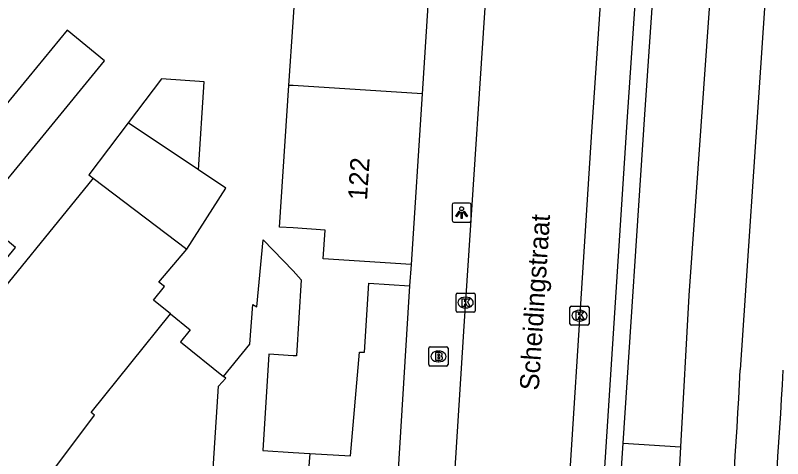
# Model space of a CAD drawing. Extents: x 160158 to 160921, y 381517 to 382041.
# Drawn here: x 160485.46 to 160525.63, y 381829.34 to 381852.53 of the extents above; entities that cross this region are included whole.
import ezdxf

# ---------------------------------------------------------------- set-up
doc = ezdxf.new("R2010")
doc.units = 0
for name, color, linetype in [('IMGEO_Berm_groen', 7, 'Continuous'), ('IMGEO_Berm_open', 7, 'Continuous'), ('IMGEO_Brandkraan', 7, 'Continuous'), ('IMGEO_Kolk', 7, 'Continuous'), ('IMGEO_Lichtpunt', 7, 'Continuous'), ('IMGEO_Openbare_ruimte_label', 7, 'Continuous'), ('IMGEO_Pand', 7, 'Continuous'), ('IMGEO_Pand_nummerreeks', 7, 'Continuous'), ('IMGEO_Parkeervlak_open', 7, 'Continuous'), ('IMGEO_Rijbaan_lokaal_open', 7, 'Continuous'), ('IMGEO_Voetpad_open', 7, 'Continuous')]:
    doc.layers.add(name, color=color, linetype=linetype)

msp = doc.modelspace()

# ---------------------------------------------------------------- linework, layer by layer
at = {"layer": 'IMGEO_Berm_groen'}
for points in [[(160532.014, 381924.443), (160531.525, 381926.029), (160530.481, 381926.358), (160529.573, 381925.76), (160523.404, 381833.99)], [(160523.346, 381875.055), (160520.714, 381837.873), (160520.28, 381829.952)], [(160520.28, 381829.952), (160520.063, 381825.981), (160517.843, 381805.586), (160514.368, 381782.689), (160510.053, 381758.978), (160509.927, 381757.953)], [(160517.274, 381830.144), (160520.28, 381829.952)]]:
    msp.add_lwpolyline(points, dxfattribs=at)
for centre, radius, start, end in [((160092.55, 381856.358), 431.434, 350.65138, 357.02816), ((160083.837, 381858.802), 442.519, 350.5442, 356.78225), ((160153.748, 381850.796), 375.027, 349.97715, 357.39851)]:
    msp.add_arc(centre, radius, start, end, dxfattribs=at)
at = {"layer": 'IMGEO_Berm_open'}
for points in [[(160517.274, 381830.144), (160518.408, 381847.341), (160520.311, 381874.994), (160520.319, 381875.157), (160520.327, 381875.319)], [(160513.86, 381817.808), (160516.446, 381817.577), (160517.274, 381830.144)]]:
    msp.add_lwpolyline(points, dxfattribs=at)
at = {"layer": 'IMGEO_Brandkraan'}
for p, q in [((160507.106, 381834.263), (160507.106, 381835.115)), ((160507.181, 381835.189), (160508.033, 381835.189)), ((160508.107, 381835.115), (160508.107, 381834.263)), ((160507.594, 381834.969), (160507.619, 381834.969)), ((160507.617, 381834.409), (160507.592, 381834.409)), ((160508.033, 381834.189), (160507.181, 381834.189))]:
    msp.add_line(p, q, dxfattribs=at)
for points in [[(160507.106, 381834.263), (160507.106, 381835.115)], [(160507.181, 381835.189), (160508.033, 381835.189)], [(160508.107, 381835.115), (160508.107, 381834.263)], [(160507.454, 381834.889), (160507.454, 381834.489), (160507.667, 381834.489)], [(160507.685, 381834.889), (160507.454, 381834.889)], [(160507.633, 381834.808), (160507.579, 381834.808), (160507.579, 381834.732)], [(160507.579, 381834.732), (160507.632, 381834.732)], [(160507.641, 381834.656), (160507.579, 381834.656), (160507.579, 381834.575)], [(160507.579, 381834.575), (160507.641, 381834.575)], [(160508.033, 381834.189), (160507.181, 381834.189)]]:
    msp.add_lwpolyline(points, dxfattribs=at)
for centre, radius, start, end in [((160507.183, 381835.113), 0.0765, 91.552, 178.448), ((160507.183, 381835.113), 0.0765, 91.552, 178.448), ((160508.031, 381835.113), 0.0765, 1.552, 88.448), ((160508.031, 381835.113), 0.0765, 1.552, 88.448), ((160507.634, 381834.77), 0.0379, 267.8285, 90.9355), ((160507.689, 381834.744), 0.145, 59.4692, 91.5367), ((160507.714, 381834.791), 0.0922, 285.5137, 58.1501), ((160507.719, 381834.599), 0.105, 301.3115, 78.989), ((160507.642, 381834.615), 0.0404, 269.8759, 90.5077), ((160507.673, 381834.74), 0.251, 268.6676, 293.5347), ((160507.183, 381834.265), 0.0765, 181.552, 268.448), ((160507.183, 381834.265), 0.0765, 181.552, 268.448), ((160508.031, 381834.265), 0.0765, 271.552, 358.448), ((160508.031, 381834.265), 0.0765, 271.552, 358.448)]:
    msp.add_arc(centre, radius, start, end, dxfattribs=at)
for centre, major_axis, ratio, start_param, end_param in [((160507.593, 381834.689), (-0.387, 0.002), 0.722429, 4.712389, 7.853982), ((160507.618, 381834.689), (-0.39, 0.002), 0.717154, 1.570796, 4.712389)]:
    msp.add_ellipse(centre, major_axis=major_axis, ratio=ratio, start_param=start_param, end_param=end_param, dxfattribs=at)
at = {"layer": 'IMGEO_Kolk'}
for p, q in [((160508.527, 381837.08), (160508.527, 381837.932)), ((160508.602, 381838.006), (160509.454, 381838.006)), ((160509.528, 381837.932), (160509.528, 381837.08)), ((160509.015, 381837.786), (160509.04, 381837.786)), ((160509.038, 381837.226), (160509.013, 381837.226)), ((160514.489, 381836.397), (160514.489, 381837.249)), ((160514.564, 381837.323), (160515.416, 381837.323)), ((160514.977, 381837.103), (160515.002, 381837.103)), ((160515.49, 381837.249), (160515.49, 381836.397)), ((160509.454, 381837.006), (160508.602, 381837.006)), ((160515.416, 381836.323), (160514.564, 381836.323)), ((160515, 381836.543), (160514.975, 381836.543))]:
    msp.add_line(p, q, dxfattribs=at)
for points in [[(160508.527, 381837.08), (160508.527, 381837.932)], [(160508.602, 381838.006), (160509.454, 381838.006)], [(160509.528, 381837.932), (160509.528, 381837.08)], [(160508.848, 381837.706), (160508.971, 381837.706), (160508.971, 381837.555), (160509.101, 381837.706), (160509.265, 381837.706), (160509.119, 381837.555), (160509.272, 381837.306), (160509.12, 381837.306), (160509.035, 381837.47), (160508.971, 381837.403), (160508.971, 381837.306), (160508.848, 381837.306), (160508.848, 381837.706)], [(160514.489, 381836.397), (160514.489, 381837.249)], [(160514.564, 381837.323), (160515.416, 381837.323)], [(160515.49, 381837.249), (160515.49, 381836.397)], [(160509.454, 381837.006), (160508.602, 381837.006)], [(160514.81, 381837.023), (160514.933, 381837.023), (160514.933, 381836.872), (160515.063, 381837.023), (160515.227, 381837.023), (160515.081, 381836.872), (160515.234, 381836.623), (160515.082, 381836.623), (160514.997, 381836.787), (160514.933, 381836.72), (160514.933, 381836.623), (160514.81, 381836.623), (160514.81, 381837.023)], [(160515.416, 381836.323), (160514.564, 381836.323)]]:
    msp.add_lwpolyline(points, dxfattribs=at)
for centre, start, end in [((160508.604, 381837.93), 91.552, 178.448), ((160508.604, 381837.93), 91.552, 178.448), ((160509.452, 381837.93), 1.552, 88.448), ((160509.452, 381837.93), 1.552, 88.448), ((160508.604, 381837.082), 181.552, 268.448), ((160508.604, 381837.082), 181.552, 268.448), ((160509.452, 381837.082), 271.552, 358.448), ((160509.452, 381837.082), 271.552, 358.448), ((160514.566, 381837.247), 91.552, 178.448), ((160514.566, 381837.247), 91.552, 178.448), ((160515.414, 381837.247), 1.552, 88.448), ((160515.414, 381837.247), 1.552, 88.448), ((160514.566, 381836.399), 181.552, 268.448), ((160514.566, 381836.399), 181.552, 268.448), ((160515.414, 381836.399), 271.552, 358.448), ((160515.414, 381836.399), 271.552, 358.448)]:
    msp.add_arc(centre, 0.0765, start, end, dxfattribs=at)
for centre, major_axis, ratio, start_param, end_param in [((160509.014, 381837.506), (-0.387, 0.002), 0.722429, 4.712389, 7.853982), ((160509.039, 381837.506), (-0.39, 0.002), 0.717154, 1.570796, 4.712389), ((160514.976, 381836.823), (-0.387, 0.002), 0.722429, 4.712389, 7.853982), ((160515.001, 381836.823), (-0.39, 0.002), 0.717154, 1.570796, 4.712389)]:
    msp.add_ellipse(centre, major_axis=major_axis, ratio=ratio, start_param=start_param, end_param=end_param, dxfattribs=at)
at = {"layer": 'IMGEO_Lichtpunt'}
for p, q in [((160509.224, 381842.716), (160508.416, 381842.716)), ((160509.224, 381842.716), (160508.416, 381842.716)), ((160508.322, 381842.621), (160508.322, 381841.814)), ((160508.322, 381842.621), (160508.322, 381841.814)), ((160509.318, 381841.814), (160509.318, 381842.621)), ((160509.318, 381841.814), (160509.318, 381842.621)), ((160508.416, 381841.72), (160509.224, 381841.72)), ((160508.416, 381841.72), (160509.224, 381841.72))]:
    msp.add_line(p, q, dxfattribs=at)
for points in [[(160508.696, 381842.285), (160508.735, 381842.257), (160508.547, 381841.995), (160508.509, 381842.022), (160508.696, 381842.285)], [(160508.798, 381842.237), (160508.845, 381842.237), (160508.845, 381841.915), (160508.798, 381841.915), (160508.798, 381842.237)], [(160508.908, 381842.257), (160508.946, 381842.284), (160509.133, 381842.022), (160509.094, 381841.994), (160508.908, 381842.257)]]:
    msp.add_lwpolyline(points, dxfattribs=at)
msp.add_circle((160508.821, 381842.419), 0.0994, dxfattribs=at)
for centre, start, end in [((160508.416, 381842.621), 90, 180), ((160508.416, 381842.621), 90, 180), ((160509.224, 381842.621), 0, 90), ((160509.224, 381842.621), 0, 90), ((160508.416, 381841.814), 180, 270), ((160508.416, 381841.814), 180, 270), ((160509.224, 381841.814), 270, 0), ((160509.224, 381841.814), 270, 360)]:
    msp.add_arc(centre, 0.0946, start, end, dxfattribs=at)
at = {"layer": 'IMGEO_Pand'}
for points in [[(160499.779, 381848.873), (160500, 381852.181), (160500.273, 381856.394), (160502.782, 381856.231), (160502.874, 381857.649), (160500.129, 381858.808), (160502.175, 381861.609)], [(160507.527, 381860.411), (160506.751, 381848.424)], [(160480.304, 381834.119), (160483.484, 381837.978), (160485.473, 381840.393), (160483.459, 381842.052), (160486.907, 381846.238), (160490.129, 381850.149), (160488.178, 381851.756), (160484.957, 381847.845)], [(160495.039, 381844.456), (160495.348, 381849.064), (160493.113, 381849.214), (160491.363, 381846.903)], [(160506.173, 381839.496), (160501.57, 381839.794), (160501.668, 381841.304), (160500.001, 381841.412), (160499.283, 381841.461), (160499.779, 381848.873)], [(160506.751, 381848.424), (160500, 381848.859), (160499.779, 381848.873)], [(160506.751, 381848.424), (160506.173, 381839.496)], [(160491.363, 381846.903), (160489.303, 381844.183), (160489.523, 381844.017)], [(160495.039, 381844.456), (160491.363, 381846.903)], [(160494.435, 381840.297), (160496.477, 381843.499), (160495.039, 381844.456)], [(160489.523, 381844.017), (160483.249, 381836.314), (160481.128, 381833.441)], [(160489.523, 381844.017), (160494.435, 381840.297)], [(160496.361, 381833.644), (160497.725, 381835.337), (160497.884, 381837.409), (160498.102, 381837.278), (160498.428, 381840.783), (160500, 381839.172), (160500.415, 381838.702), (160500.169, 381834.713), (160500, 381834.723), (160498.719, 381834.802), (160498.409, 381829.769), (160500, 381829.671), (160500.868, 381829.617)], [(160493.577, 381836.913), (160492.694, 381837.625), (160493.273, 381838.344), (160492.975, 381838.584), (160494.435, 381840.297)], [(160500.868, 381829.617), (160503.001, 381829.486), (160503.479, 381834.92), (160503.742, 381834.909), (160503.965, 381838.518), (160506.091, 381838.386)], [(160506.091, 381838.386), (160505.533, 381829.33), (160505.049, 381821.483)], [(160487.416, 381828.497), (160487.323, 381828.564), (160489.609, 381831.618), (160489.422, 381831.756), (160493.577, 381836.913)], [(160493.577, 381836.913), (160494.608, 381836.082), (160494.108, 381835.46), (160496.361, 381833.644)], [(160495.382, 381822.078), (160496.097, 381833.132), (160496.469, 381833.557), (160496.361, 381833.644)], [(160500.868, 381829.617), (160500.249, 381821.779)]]:
    msp.add_lwpolyline(points, dxfattribs=at)
at = {"layer": 'IMGEO_Parkeervlak_open'}
msp.add_lwpolyline([(160519.387, 381875.229), (160517.479, 381847.224), (160515.937, 381823.215)], dxfattribs=at)
at = {"layer": 'IMGEO_Rijbaan_lokaal_open'}
for points in [[(160507.968, 381820.837), (160508.946, 381836.272), (160510.338, 381857.185), (160510.794, 381864.027), (160511.622, 381876.467)], [(160513.972, 381820.522), (160515.631, 381846.447), (160517.644, 381875.952)]]:
    msp.add_lwpolyline(points, dxfattribs=at)
at = {"layer": 'IMGEO_Voetpad_open'}
msp.add_lwpolyline([(160506.173, 381839.496), (160506.091, 381838.386)], dxfattribs=at)

# ---------------------------------------------------------------- texts
at = {"layer": 'IMGEO_Openbare_ruimte_label'}
msp.add_text('Scheidingstraat', height=1, rotation=86.2736, dxfattribs=at).set_placement((160512.853, 381832.891))
at = {"layer": 'IMGEO_Pand_nummerreeks'}
msp.add_text('122', height=1, rotation=86.2958, dxfattribs=at).set_placement((160503.864, 381842.836))

doc.saveas('drawing.dxf')
